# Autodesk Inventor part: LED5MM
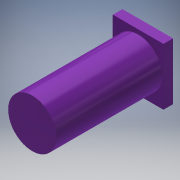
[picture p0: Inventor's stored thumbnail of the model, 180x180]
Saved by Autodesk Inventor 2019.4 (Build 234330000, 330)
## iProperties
Created: 2019-11
Part Number: LED5MM
Material: Generic
Document SubType Name: Modeling
Designer: Willist
Density: 1 g/cm^3
Appearance: LED5MM, LED5MM
Author: Willist
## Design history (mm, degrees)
sketch "LED5MM, LED5MM_28"
  geometry: L1 (-2.616, 3.302)-(2.642, 3.302); L2 (2.642, 3.302)-(2.642, -2.616); L3 (2.642, -2.616)-(-2.616, -2.616); L4 (-2.616, -2.616)-(-2.616, 3.302)
  constraints: 8 end point
extrude "Extrusion1" join sketch "LED5MM, LED5MM_28" distance "d0" = 1; taper "d1" = 0 deg
sketch "Sketch2"
  geometry: L1 (2.642, 3.302)-(-2.616, 3.302) reference; L2 (-2.616, -2.616)-(2.642, -2.616) reference; L3 (-2.616, 3.302)-(2.642, 3.302); L4 (2.642, 3.302)-(2.642, -2.616); L5 (2.642, -2.616)-(-2.616, -2.616); L6 (-2.616, -2.616)-(-2.616, 3.302); C1 r 2.5 at (0.013, 0.343); 1 further point
  constraints: 8 end point, 2 parallel, 1 centre point, 1 horizontal, 1 perpendicular
  dimensions: "d2" = 5 diameter of C1
extrude "Extrusion2" join sketch "Sketch2" distance "d3" = 11; taper "d4" = 0 deg
body "Solid1"
